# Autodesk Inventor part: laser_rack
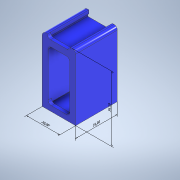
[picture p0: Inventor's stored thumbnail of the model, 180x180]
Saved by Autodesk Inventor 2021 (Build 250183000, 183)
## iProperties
Created: 2026-10
Part Number: laser_rack
Material: Generic
Document SubType Name: Modeling
Designer: alolo
Density: 1 g/cm^3
Appearance: Default
Author: alolo
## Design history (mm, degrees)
node "Annotations"
  node "Linear Dimension 1" dims "d7" = 39.1, "d28" = 25 (derived)
  node "Linear Dimension 2" dims "d7" = 39.1, "d30" = 39.1 (derived)
  node "Linear Dimension 3" dims "d7" = 39.1, "d33" = 20 (derived)
sketch "Sketch1"
  geometry: L1 (0, 0)-(20, 0); L2 (20, 0)-(20, 37.1); L3 (0, 37.1)-(0, 0); L4 (20, 37.1)-(20, 35.4); L5 (17.75, 35.4)-(2.25, 35.4); L6 (0, 35.4)-(0, 37.1); L7 (3, 37.1)-(3, 39.1); L8 (17, 37.1)-(17, 39.1); L9 (2, 39.1)-(3, 39.1); L10 (2.25, 37.1)-(3, 37.1); L11 (17, 37.1)-(17.75, 37.1); L12 (17, 39.1)-(18, 39.1); L13 (17.75, 37.1)-(17.75, 35.4); L14 (17.75, 35.4)-(2.25, 35.4); L15 (2.25, 35.4)-(2.25, 37.1); L16 (17.75, 1.4)-(10, 1.4); L17 (17.75, 1.4)-(10, 1.4); L18 (16.5, 3.1)-(17.75, 3.1); L19 (17.75, 3.1)-(17.75, 1.4); L20 (16.5, 33.4)-(10, 33.4); L21 (10, 0)-(10, 35.4); L22 (16.5, 3.1)-(16.5, 33.4); L23 (3.5, 3.1)-(3.5, 33.4); L24 (3.5, 33.4)-(10, 33.4); L25 (2.25, 3.1)-(2.25, 1.4); L26 (2.25, 1.4)-(10, 1.4); L27 (3.5, 3.1)-(2.25, 3.1); A1 r 2 centre (2, 37.1) between (2, 39.1) and (0, 37.1); A2 r 2 centre (18, 37.1) between (20, 37.1) and (18, 39.1); 4 further points
  constraints: 54 end point, 9 perpendicular, 8 point on line, 6 parallel, 5 horizontal, 4 midpoint, 4 point on circle, 4 symmetric about line, 4 tangent, 2 centre point, 2 collinear, 2 vertical, 1 coincident, 1 equal radius, 1 vertical alignment
  dimensions: "d7" = 39.1 distance of L1.end point (20, 39.1); "d8" = 3 distance between parallel lines of L3 L7; "d9" = 3 distance between parallel lines of L2 L8; "d10" = 15.5 distance of L5.start L5.end; "d13" = 2 radius of A1 (derived); "d15" = 1.4 distance between parallel lines of L16 L1; "d16" = 2 distance between parallel lines of L5 L20; "d21" = 7.75 distance of L16.start L16.end; "d22" = 6.5 distance of L20.start L20.end
extrude "Extrusion1" new body sketch "Sketch1" distance "d11" = 25; taper "d12" = 0 deg
sketch "Sketch3"
  geometry: L1 (2.25, 1.4)-(2.25, 3.1) reference; L2 (17.75, 3.1)-(17.75, 1.4) reference; L3 (2.25, 3.1)-(17.75, 3.1); L4 (17.75, 3.1)-(17.75, 1.4); L5 (17.75, 1.4)-(2.25, 1.4); L6 (2.25, 1.4)-(2.25, 3.1); L7 (2.25, 37.1)-(3, 37.1) reference; L8 (17.75, 35.4)-(2.25, 35.4) reference; L9 (2.25, 37.1)-(17.75, 37.1); L10 (17.75, 37.1)-(17.75, 35.4); L11 (17.75, 35.4)-(2.25, 35.4); L12 (2.25, 35.4)-(2.25, 37.1); 5 further points
  constraints: 16 end point, 4 parallel, 2 horizontal, 2 perpendicular
extrude "Extrusion3" join sketch "Sketch3" distance "d23" = 2; taper "d24" = 0 deg
fillet "Fillet3" dims "d25" = 2
body "Solid1"
other parameters: "d4" = 1.7, "d6" = 2, "d26" = 0 (derived), "d29" = 7.96182 (derived), "d31" = 0 (derived)
